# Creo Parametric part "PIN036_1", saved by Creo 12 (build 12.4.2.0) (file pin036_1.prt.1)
Units: Custom; MM, KILOGRAM, SECS

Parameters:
  PTC_WM_ITERATION = "0"
  PTC_WM_VERSION = "-.0"
  PTC_WM_LIFECYCLE_STATE = "In Work"
  PTC_WM_LIFECYCLE = "MO_CADDocument"
  PTC_WM_CREATED_BY = "Maximilian Roepper (Z0017RMS: MO)"
  PTC_WM_CREATED_ON = "18-Sep-26 11:36:42 AM"
  PTC_WM_MODIFIED_BY = "Maximilian Roepper (Z0017RMS: MO)"
  PTC_WM_MODIFIED_ON = "18-Sep-26 11:36:46 AM"
  PDMLINKNUMBER = "PDM000071455265"
  PTC_WM_NAME = "pin036_1.prt"
  PTC_WM_NUMBER = "PDM000071455265"

Other parameters: WEIGHT, WEIGHT_FACTOR, WEIGHT_ADD, _MASS_TEMP, _DIFF_TEMP, MC_ERRORS, SUPPLIER

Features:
  1. coordinate system
  2. datum plane "PRT_YZ"
  3. datum plane "PRT_XY"
  4. datum plane "PRT_XZ"
  5. coordinate system
  6. datum axis
  7. datum axis
  8. datum axis
  9. coordinate system
  10. imported feature

Other named items: PRT, SIEMENS_MO, DRW_VIEW_ORG, PRT_X, PRT_Y, PRT_Z, CS0, ROUGH_GROB

Layers: 00_STD_CSYS-KSYS, 01_STD_PLANES-EBENEN, 02_STD_AXES-ACHSEN, 03_STD_CSYS-KSYS, 24_IMPORT_FEAT-IMPORT_KE

Surfaces: 10 plane, 4 cylinder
